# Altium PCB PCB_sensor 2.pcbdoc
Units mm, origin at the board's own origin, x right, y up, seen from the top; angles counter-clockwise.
Board outline 176.12 x 80.64 mm, 2 copper layers (Top Layer, Bottom Layer); 20 components, 19 nets, 76 pads, 0 vias.
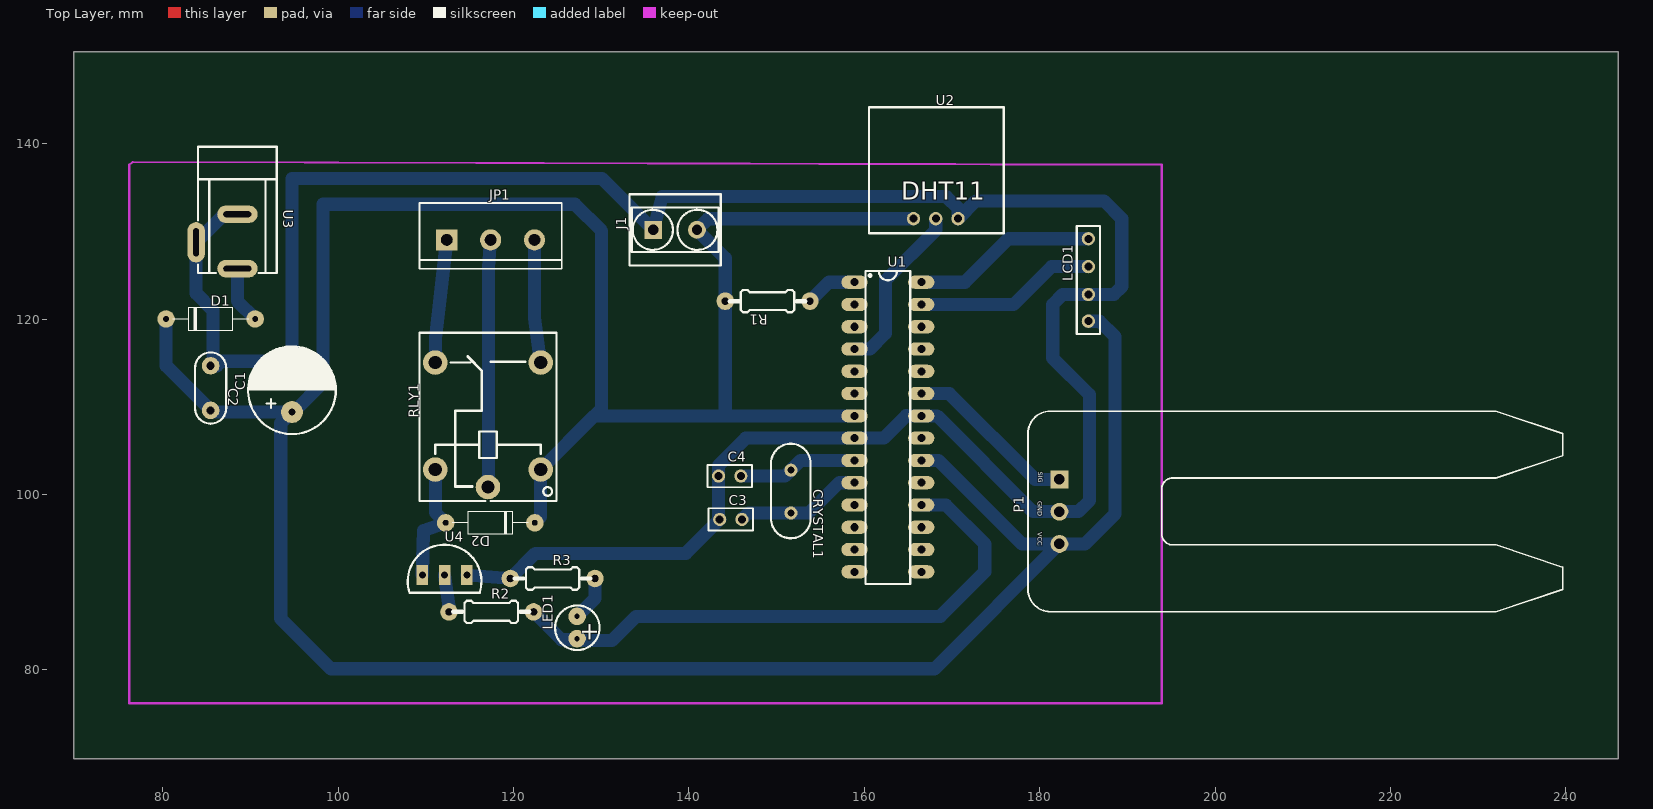
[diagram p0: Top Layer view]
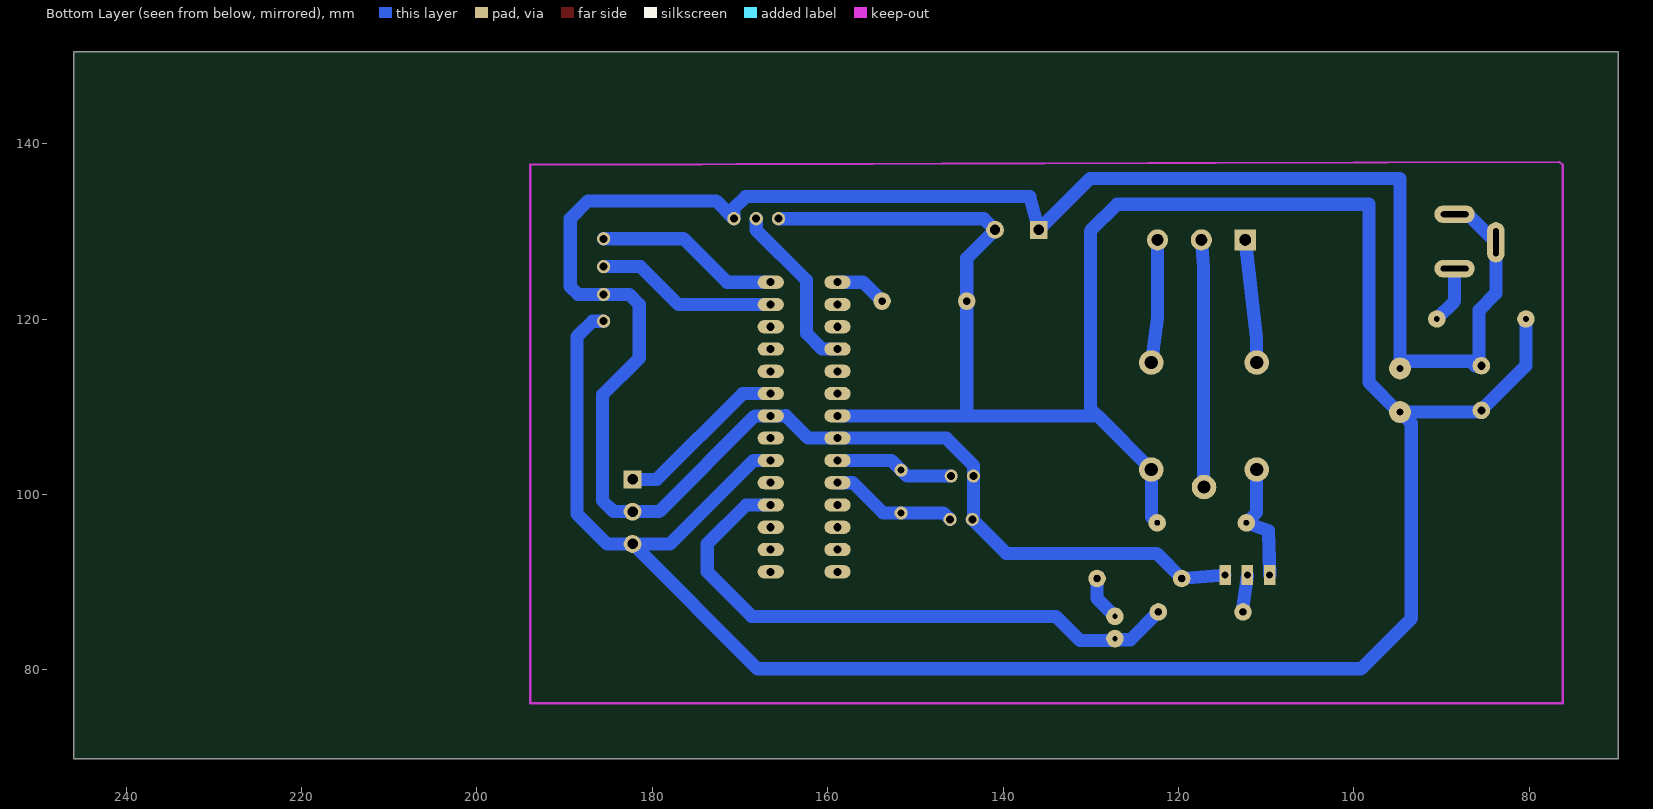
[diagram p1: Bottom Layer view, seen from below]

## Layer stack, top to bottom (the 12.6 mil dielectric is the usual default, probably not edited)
Top Layer: signal copper (thickness not stored)
Dielectric: dielectric 0.32, FR-4, Dk 4.8
Bottom Layer: signal copper (thickness not stored)

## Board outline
245.973,69.85 69.85,69.85 69.85,150.495 245.973,150.495

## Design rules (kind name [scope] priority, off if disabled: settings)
BoardOutlineClearance Default [All] p0: genericclearance=0.254 ignorepadtopadclearanceinfootprint=FALSE except(0: Region-CutoutEdge Arc-SplitContinuation Track-SplitContinuation SMDPad-SplitContinuation THPad-SplitContinuation Via-SplitContinuation Fill-SplitContinuation Poly-SplitContinuation Region-SplitContinuation Text-SplitContinuation; 1.001: Track-OutlineEdge SMDPad-OutlineEdge THPad-OutlineEdge Via-OutlineEdge Fill-OutlineEdge Region-OutlineEdge Poly-OutlineEdge Text-OutlineEdge Sheet-OutlineEdge Hole-OutlineEdge Track-CutoutEdge SMDPad-CutoutEdge THPad-CutoutEdge Via-CutoutEdge Fill-CutoutEdge Poly-CutoutEdge Text-CutoutEdge Sheet-CutoutEdge Hole-CutoutEdge)
Clearance Default [All] p1: gap=0.178 ignorepadtopadclearanceinfootprint=FALSE except(0: Region-Region; 1.001: Track-Track SMDPad-Track THPad-Track Via-Track Fill-Track Region-Track Poly-Track Text-Track Sheet-Track Hole-Track Track-SMDPad SMDPad-SMDPad THPad-SMDPad Via-SMDPad Fill-SMDPad Region-SMDPad Poly-SMDPad Text-SMDPad Sheet-SMDPad Hole-SMDPad Track-THPad SMDPad-THPad THPad-THPad Via-THPad Fill-THPad Region-THPad Poly-THPad Text-THPad Sheet-THPad Hole-THPad Track-Via SMDPad-Via THPad-Via Via-Via Fill-Via Region-Via Poly-Via Text-Via Sheet-Via Hole-Via Track-Fill SMDPad-Fill THPad-Fill Via-Fill Fill-Fill Region-Fill Poly-Fill Text-Fill Sheet-Fill Hole-Fill Track-Region SMDPad-Region THPad-Region Via-Region Fill-Region Poly-Region Text-Region Sheet-Region Hole-Region Track-Poly SMDPad-Poly THPad-Poly Via-Poly Fill-Poly Region-Poly Poly-Poly Text-Poly Sheet-Poly Hole-Poly Track-Text SMDPad-Text THPad-Text Via-Text Fill-Text Region-Text Poly-Text Text-Text Sheet-Text Hole-Text Track-Sheet SMDPad-Sheet THPad-Sheet Via-Sheet Fill-Sheet Region-Sheet Poly-Sheet Text-Sheet Sheet-Sheet Hole-Sheet Track-Hole SMDPad-Hole THPad-Hole Via-Hole Fill-Hole Region-Hole Poly-Hole Text-Hole Sheet-Hole Hole-Hole)
PasteMaskExpansion Common [All] p1: expansion=0
PlaneConnect Default [All] p1: planeconnectstyle=Relief reliefexpansion=0.508 reliefentries=4 reliefconductorwidth=0 reliefairgap=0.025
PolygonConnect Default [All] p1: connectstyle=Relief reliefentries=4 reliefconductorwidth=0 polygonreliefangle="90 Angle" airgapwidth=10
RoutingVias Default [All] p1: viastyle="Through Hole" holewidth=19.685 minholewidth=19.685 maxholewidth=2362 width=78.74 minwidth=78.74 maxwidth=3938
SolderMaskExpansion Common [All] p1: useseparateexpansions=TRUE expansion=2 expansionbottom=2
Width Default [All] p1: maxlimit=1000 minlimit=59 preferedwidth=59

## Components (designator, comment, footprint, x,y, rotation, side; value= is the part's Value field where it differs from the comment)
C1 "1000uF" "CAP1000UFX25V-10X20(5MM, D-0.8)" 94.742,111.887 r90 top
C2 "104" "NP CAP-8*3.5-5.08MM" 85.471,112.141 r270 top
C3 "22pf" CAP-TH_L5.0-W2.5-P2.54-D0.7 144.78,97.155 r0 top
C4 "22pf" CAP-TH_L5.0-W2.5-P2.54-D0.7 144.653,102.108 r0 top
CRYSTAL1 "mhz" CRYSTAL-TH_L10.8-W4.5-P4.88 151.638,100.33 r270 top
D1 "1N4007" 1N4007 85.471,120.015 r0 top
D2 "1N4007" 1N4007 117.348,96.774 r180 top
J1 "Screw Terminal" H2-5.0-10.5X8.0MM 138.43,130.175 r90 top
JP1 "SCREWTERMINAL-5MM-3" SCREWTERMINAL-5MM-3 112.395,129.032 r0 top
LCD1 "_" "FP LCDI2C" 185.547,119.761 r90 top
LED1 "LED 5MM" LED-5MM-5MM 129.794,86.106 r90 top
P1 "Soil Moisture Sensor" "SOIL MOISTURE SENSOR" 182.245,98.044 r90 top
R1 "10k" RESISTOR-1/4W 148.971,122.047 r180 top
R2 "100e" RESISTOR-1/4W 117.475,86.614 r0 top
R3 "220e" RESISTOR-1/4W 124.46,90.424 r0 top
RLY1 "Реле пылесоса 12В" RELAY-TH_SRD-XXVDC-XL-C 117.094,107.95 r90 top
U1 "ATMEGA328 DIP" ATMEGA328P 162.687,107.696 r0 top
U2 "DHT11" DHT11 165.608,131.445 r0 top
U3 "BARREL JACK CONECTOR" "BARREL JACK_FOOTPRINT" 92.964,139.573 r270 top
U4 "TRANSISTOR" TRANSISTOR 112.141,90.805 r0 top

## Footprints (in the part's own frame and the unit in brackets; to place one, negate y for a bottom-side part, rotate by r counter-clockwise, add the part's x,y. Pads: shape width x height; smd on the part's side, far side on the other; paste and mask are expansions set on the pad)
1N4007 [mm]
  round 2 hole 0.61 slot 0.615 at 0 deg: A(5.08,0) K(-5.08,0)
  silkscreen extent -4.32,-1.27 4.32,1.27
ATMEGA328P [mm]
  oval 3x1.5 hole 0.914: 1(-3.81,16.51) 2(-3.81,13.97) 3(-3.81,11.43) 4(-3.81,8.89) 5(-3.81,6.35) 6(-3.81,3.81) 7(-3.81,1.27) 8(-3.81,-1.27) 9(-3.81,-3.81) 10(-3.81,-6.35) 11(-3.81,-8.89) 12(-3.81,-11.43) 13(-3.81,-13.97) 14(-3.81,-16.51) 15(3.81,-16.51) 16(3.81,-13.97) 17(3.81,-11.43) 18(3.81,-8.89) 19(3.81,-6.35) 20(3.81,-3.81) 21(3.81,-1.27) 22(3.81,1.27) 23(3.81,3.81) 24(3.81,6.35) 25(3.81,8.89) 26(3.81,11.43) 27(3.81,13.97) 28(3.81,16.51)
  silkscreen extent -2.54,-17.91 2.54,17.78
"BARREL JACK_FOOTPRINT" [mm]
  oval 2x4.6 hole 0.635 slot 3.175 at 90 deg: 1(13.82,-4.445) 2(7.62,-4.445)
  oval 4.6x2 hole 0.635 slot 3.175 at 0 deg: 3(10.82,-9.145)
  silkscreen extent -0.08,-8.94 14.32,0.06
"CAP1000UFX25V-10X20(5MM, D-0.8)" [mm]
  round 2.5 hole 0.8: 1(-2.492,0) 2(2.492,0)
  silkscreen extent -5,-5.1 5,5
CAP-TH_L5.0-W2.5-P2.54-D0.7 [mm]
  round 1.5 hole 0.9: 1(-1.27,0) 2(1.27,0)
  silkscreen extent -2.54,-1.27 2.54,1.27
CRYSTAL-TH_L10.8-W4.5-P4.88 [mm]
  round 1.5 hole 0.8: 1(-2.44,0) 2(2.44,0)
  silkscreen extent -5.46,-2.28 5.32,2.24
DHT11 [mil]
  round 60 hole 36: 1(0,0) 2(100,0) 3(200,0)
  silkscreen extent -200,-65 405,500
"FP LCDI2C" [mil]
  round 60 hole 36: 1(0,0) 2(120,0) 3(245,0) 4(370,0)
  silkscreen extent -58,-52 428,53
H2-5.0-10.5X8.0MM [mil]
  rect 80x80 hole 46: 1(0,98)
  round 80 hole 46: 2(0,-98)
  silkscreen extent -160,-205 160,205
LED-5MM-5MM [mm]
  round 2 hole 0.6: 1(-2.54,2.54) 2(0,2.54)
  silkscreen extent -3.83,-0.02 1.24,5.06
"NP CAP-8*3.5-5.08MM" [mm]
  round 2 hole 0.914: 1(-2.54,0) 2(2.54,0)
  silkscreen extent -4.06,-1.78 4.06,1.78
RELAY-TH_SRD-XXVDC-XL-C [mil]
  round 110 hole 60: 1(-200.79,-236.22) 2(279.53,-236.19) 3(279.53,236.2) 4(-200.79,236.22) 5(-279.53,0)
  silkscreen extent -342,-307 413,307
RESISTOR-1/4W [mm]
  round 2 hole 0.8 slot 0.805 at 0 deg: 1(-4.826,0) 2(4.826,0)
  silkscreen extent -4.32,-1.27 4.32,1.27
SCREWTERMINAL-5MM-3 [mil]
  rect 95x95 hole 51.18 slot 51.38 at 0 deg: 1(0,0)
  round 95 hole 51.18 slot 51.38 at 0 deg: 2(196.85,0) 3(393.7,0)
  silkscreen extent -122,-130 516,165
"SOIL MOISTURE SENSOR" [mil]
  rect 80x80 hole 47.2: 1(145.01,-0.01)
  round 80 hole 47.2: 2(0.01,0) 3(-144.99,0)
  silkscreen extent -449,-2259 451,141
TRANSISTOR [mm]
  rect 1.3x2.3 hole 0.8: 1(-2.54,0) 2(0,0) 3(2.54,0)
  silkscreen extent -4.2,-2 4.2,3.47

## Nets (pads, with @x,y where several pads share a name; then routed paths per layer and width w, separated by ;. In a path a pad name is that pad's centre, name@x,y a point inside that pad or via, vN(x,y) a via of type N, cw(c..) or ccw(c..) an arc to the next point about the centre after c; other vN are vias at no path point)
+5V: C1.1 C2.2 D1.K D2.K J1.2 LCD1.1 P1.3 R1.2 RLY1.1 U1.7 U1.20 U2.1 | length 375.2
  Bottom Layer w1.5: D1.K 80.391,114.681 C2.2 85.677,109.395 C1.1 ; D2.K 123.094,97.44 RLY1.1 ; U1.7 144.145,108.966 ; U2.1 142.189,131.445 J1.2 144.145,126.949 R1.2 144.145,108.966 ; U1.20 168.448,103.886 177.973,94.361 P1.3 ; LCD1.1 186.817,119.761 188.595,117.983 188.595,97.79 185.166,94.361 P1.3 ; C1.1 94.917,109.395 98.298,112.776 98.298,133.096 127,133.096 130.048,130.048 130.048,109.804 RLY1.1 ; C1.1 93.472,108.125 93.472,85.852 99.187,80.137 168.021,80.137 P1.3 ; RLY1.1 129.21,108.966 144.145,108.966
D2_A: D2.A RLY1.4 | length 14.3
  Bottom Layer w1.5: 109.601,90.805 109.728,95.885 D2.A 111.094,97.948 RLY1.4
GND: C1.2 C2.1 C3.1 C4.1 J1.1 LCD1.2 P1.2 R3.1 U1.8 U1.22 U2.3 U3.2 U3.3 | length 278.9
  Bottom Layer w1.5: U3.2 87.019,131.953 U3.3 83.819,122.937 85.725,121.031 85.725,114.935 C2.1 86.182,114.681 86.69,115.189 93.932,115.189 C1.2 94.742,136.017 130.099,136.017 J1.1 136.963,133.96 169.359,133.96 170.688,132.639 U2.3 172.72,133.477 187.325,133.477 189.357,131.445 189.357,123.698 188.468,122.809 LCD1.2 182.626,122.809 181.483,121.666 181.483,115.557 185.674,111.366 185.674,99.314 184.404,98.044 P1.2 179.224,98.044 168.302,108.966 U1.22 164.827,108.966 164.789,109.004 ; R3.1 122.496,93.286 139.641,93.286 C3.1 143.383,97.282 C4.1 143.383,103.319 146.49,106.426 U1.8 162.21,106.426 164.788,109.004
LCD1_3: LCD1.3 U1.27 | length 20.8
  Bottom Layer w1.5: U1.27 177.024,121.666 181.342,125.984 LCD1.3
LCD1_4: LCD1.4 U1.28 | length 21.1
  Bottom Layer w1.5: U1.28 171.471,124.206 176.424,129.159 LCD1.4
LED1_2: LED1.2 R3.2 | length 4.9
  Bottom Layer w1.5: LED1.2@127.458,86.31 129.286,88.138 R3.2
P1_1: P1.1 U1.23 | length 19.8
  Bottom Layer w1.5: U1.23 169.699,111.506 179.478,101.727 P1.1
Q1_2: R2.1
RLY1_2: RLY1.2 | length 14
  Bottom Layer w1.5: 122.395,129.032 122.395,120.139 RLY1.2
RLY1_3: RLY1.3 | length 14.1
  Bottom Layer w1.5: RLY1.3 111.125,117.856 112.395,129.032
RLY1_5: RLY1.5 | length 28.2
  Bottom Layer w1.5: RLY1.5 117.157,100.85 117.157,125.928 ; 117.157,125.933 117.395,129.032
S$4573: U4.2 | length 3.6
  Bottom Layer w1.5: U4.2 112.649,87.249
S$4610: U4.3 | length 5
  Bottom Layer w1.5: U4.3 119.634,90.424
U1_1: R1.1 U1.1 | length 6
  Bottom Layer w1.5: R1.1 155.956,124.206 U1.1
U1_9: C4.2 CRYSTAL1.1 U1.9 | length 13.7
  Bottom Layer w1.5: C4.2 150.976,102.108 CRYSTAL1.1 152.754,103.886 U1.9
U1_10: C3.2 CRYSTAL1.2 U1.10 | length 14.6
  Bottom Layer w1.5: C3.2 146.785,97.89 CRYSTAL1.2 153.674,97.89 157.168,101.384 ; 157.169,101.384 157.207,101.346 U1.10
U1_18: LED1.1 R2.2 U1.18 | length 67.4
  Bottom Layer w1.5: R2.2 125.476,83.439 126.102,83.439 LED1.1@126.581,83.439 ; LED1.1@127.457,83.363 131.242,83.363 133.985,86.106 168.656,86.106 173.736,91.186 173.736,94.361 169.291,98.806 U1.18
U2_2: U1.4 U2.2 | length 19.7
  Bottom Layer w1.5: U1.4 160.628,116.586 162.417,118.375 162.417,124.422 168.148,130.153 U2.2
U3_1: D1.A U3.1 | length 6.6
  Bottom Layer w1.5: U3.1 88.519,122.047 D1.A
pads on no net: JP1.1 JP1.2 JP1.3 U1.2 U1.3 U1.5 U1.6 U1.11 U1.12 U1.13 U1.14 U1.15 U1.16 U1.17 U1.19 U1.21 U1.24 U1.25 U1.26 U4.1

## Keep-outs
Board Outline Layer:
  lines w0.254: 76.2,76.2 193.914,76.2 193.914,137.597 76.581,137.922 76.2,137.597 76.2,107.95 76.2,76.2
